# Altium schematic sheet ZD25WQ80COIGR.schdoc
size 127 x 101 mm
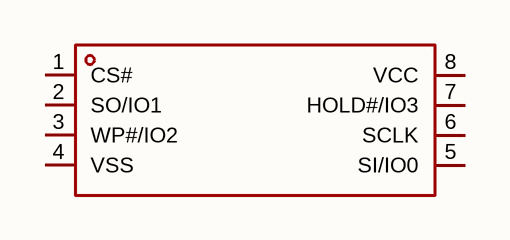
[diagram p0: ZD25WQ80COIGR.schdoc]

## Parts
U?  zd25wq80coigr  [TSSOP-8_L4.4-W3.0-P0.65-LS6.4-BL]  (value not drawn)

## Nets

Not connected (* = marked no-connect by the designer): U? 1(CS#) 2(SO/IO1) 3(WP#/IO2) 4(VSS) 5(SI/IO0) 6(SCLK) 7(HOLD#/IO3) 8(VCC)

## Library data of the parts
U? = zd25wq80coigr: 接口类型:SPI;存储容量:8Mbit;时钟频率(fc):104MHz;; Manufacturer: Zetta(澜智); AddInBom: yes; ModelId: 85577802f9634e7e85ffa2fd25a37b6f; ModelName: TSSOP-8_L4.4-W3.0-P0.65-LS6.4-BL-2; ModelTransform: 118.11,251.968,0,0,0,0,0,0,0; Interface: SPI; Memory Size: 8Mbit; Clock Frequency: 104MHz; Voltage - Supply: 1.65V~3.6V; Standby Supply Current: 1.3uA; Program / Erase Cycles: 100000次; Page Programming Time (Tpp): 1.5ms; Block Erase Time(tBE): 15ms@(64KB); Data Retention - TDR (Year): 20年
